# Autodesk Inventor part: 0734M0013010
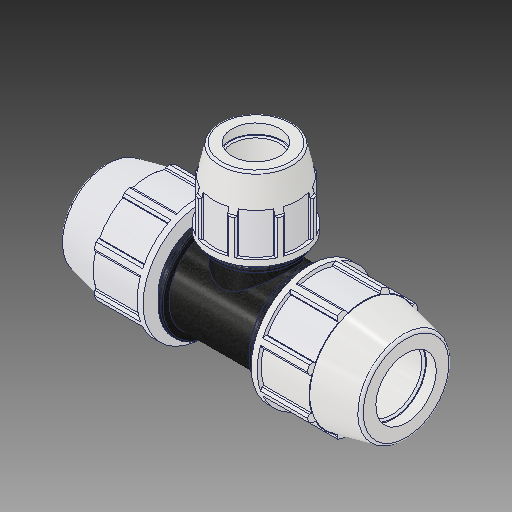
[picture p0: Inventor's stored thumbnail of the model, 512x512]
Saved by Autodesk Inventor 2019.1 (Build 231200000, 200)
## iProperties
Created: 2017-02
Part Number: 0734M0013010
Material: PVC-Piping
Description: PLASSON REDUCING TEE 1 1/4'' - 1'' - 1 1/4''
Document SubType Name: Modeling
Designer: KIM
Mass: 92.6774 g
Surface Area: 199.44 cm^2
Volume: 66.1981 cm^3
Density: 1.4 g/cm^3
Appearance: PTFE
Author: Кирилл
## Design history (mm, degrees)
derived "0734M0.ipt"
feature "Solid1::0734M0.ipt"
feature "Solid2::0734M0.ipt"
tag "TaggingFeature1"
body "Solid1"
other parameters: "d2" = 42.1, "d4" = 8.71008, "d5" = 29.26588, "d7" = 82.042, "d11" = 3.48403, "d13" = 120 deg, "d14" = 63.15, "d15" = 12 deg, "d16" = 71.37654, "d18" = 2.105, "d19" = 35 deg, "d20" = 17.5 deg, "d21" = 76.29906, "d23" = 0, "d25" = 360 deg, "d27" = 1.64084, "d33" = 0.842, "d42" = 37.62756, "d43" = 2.46126, "d46" = 1.263, "d67" = 61.5315, "d76" = 33.3, "d77" = 62.992, "d78" = 12 deg, "d79" = 96.012, "d80" = 120 deg, "d81" = 49.95, "d82" = 8.001, "d87" = 3.2004, "d89" = 24.003, "d90" = 28.8036, "d96" = 17.42017, "d98" = 58.58256, "d99" = 35 deg, "d100" = 17.5 deg, "d102" = 0, "d103" = 1.25984, "d107" = 360 deg, "d109" = 0.999, "d112" = 1.665, "d113" = 4.19947, "d114" = 0, "d117" = 209.042, "d118" = 54.80304, "d126" = 37.89, "d127" = 82.042, "d131" = 3.84048, "d132" = 29.97, "d133" = 66.04, "d135" = 0, "d138" = 4.18084, "d143" = 0, "d148" = 47.244, "d168" = 37.89, "d170" = 0, "d171" = 33.3, "d173" = 0, "d176" = 4.19947, "d177" = 0, "d_" = 42.1, "E_" = 82.042, "A_" = 96.012, "l_" = 82.042, "E_1" = 62.992, "l_1" = 66.04, "d_1" = 33.3, "H_" = 209.042
